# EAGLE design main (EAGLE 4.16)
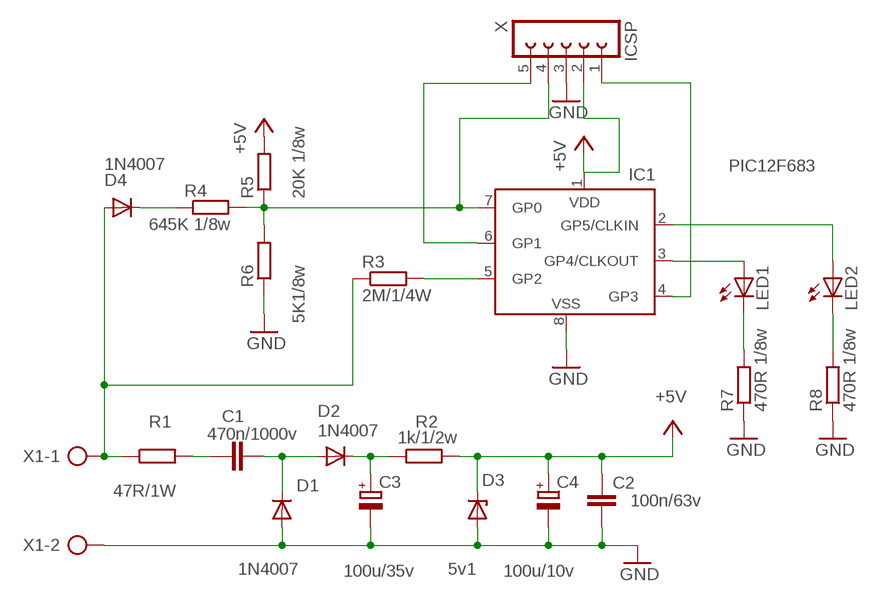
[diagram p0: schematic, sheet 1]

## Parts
C1  470n/1000v  C-EU225-113X268  [C225-113X268]
C2  100n/63v  C-EU050-025X075  [C050-025X075]
C3  100u/35v  CPOL-EUE2.5-6  [E2,5-6]
C4  100u/10v  CPOL-EUE3.5-8  [E3,5-8]
D1  1N4007  1N4004  [DO41-10]
D2  1N4007  1N4004  [DO41-10]
D3  5v1  ZENER-DIODEDO34-7  [DO34Z7]
D4  1N4007  1N4148  [DO35-10]
IC1  PIC12F683  PIC12F675SN  [SO-08]
LED1  LED3MM  [LED3MM]
LED2  LED3MM  [LED3MM]
R1  47R/1W  R-EU_0617/22  [0617/22]
R2  1k/1/2w  R-EU_0207/12  [0207/12]
R3  2M/1/4W  R-EU_0207/10  [0207/10]
R4  645K 1/8w  R-EU_0207/10  [0207/10]
R5  20K 1/8w  R-EU_0207/10  [0207/10]
R6  5K1/8w  R-EU_0207/10  [0207/10]
R7  470R 1/8w  R-EU_0207/10  [0207/10]
R8  470R 1/8w  R-EU_0207/10  [0207/10]
X  ICSP  FE05-1  [FE05-1]
X1  AK300/2  [AK300/2]

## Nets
+5V: C2.1 C4.+ D3.C IC1.1(VDD) R2.2 R5.2 X.2
GND: C2.2 C3.- C4.- D1.A D3.A IC1.8(VSS) R6.1 R7.1 R8.1 X1.2 X.3
N$1: C1.1 R1.2
N$2: C1.2 D1.C D2.A
N$3: C3.+ D2.C R2.1
N$4: D4.A R1.1 R3.1 X1.1
N$5: IC1.7(GP0) R4.2 R5.1 R6.2 X.4
N$6: D4.C R4.1
N$7: LED1.K(C) R7.2
N$8: LED2.K(C) R8.2
N$9: IC1.3(GP4/CLKOUT) LED1.A
N$10: IC1.2(GP5/CLKIN) LED2.A
N$11: IC1.5(GP2) R3.2
N$12: IC1.4(GP3) X.1
X: IC1.6(GP1) X.5

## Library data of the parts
C1 C2 = rcl:C-EU: CAPACITOR, European symbol
C3 C4 = rcl:CPOL-EU: POLARIZED CAPACITOR, European symbol
D1 D2 = diode:1N4004: DIODE
D3 = diode:ZENER-DIODE: Z-Diode
D4 = diode:1N4148: DIODE
IC1 = microchip:PIC12F6*: Data Sheet 8-Pin FLASH-Based 8-Bit CMOS Microcontrollers Source: http://www.microchip.com .. 41190c.pdf
LED1 LED2 = led:LED: LED
R1-R8 = rcl:R-EU_: RESISTOR, European symbol
X = con-lsta:FE05-1: FEMALE HEADER
X1 = con-ptr500:AK300/2: CONNECTOR

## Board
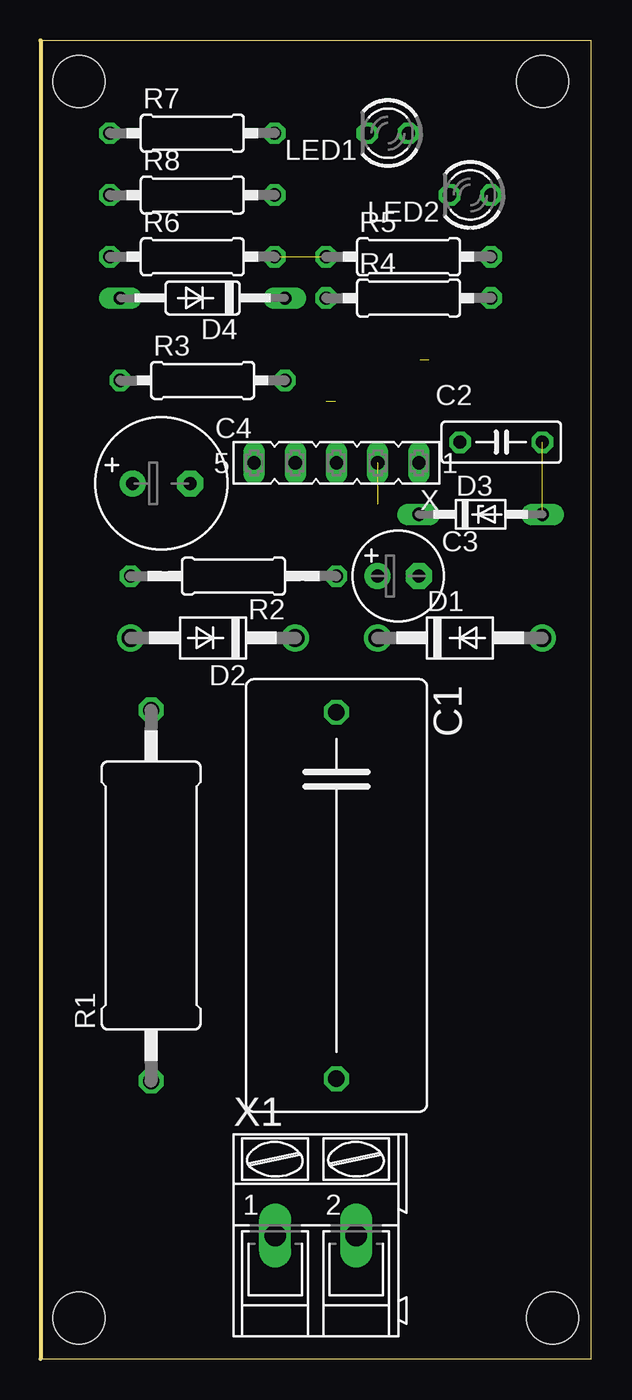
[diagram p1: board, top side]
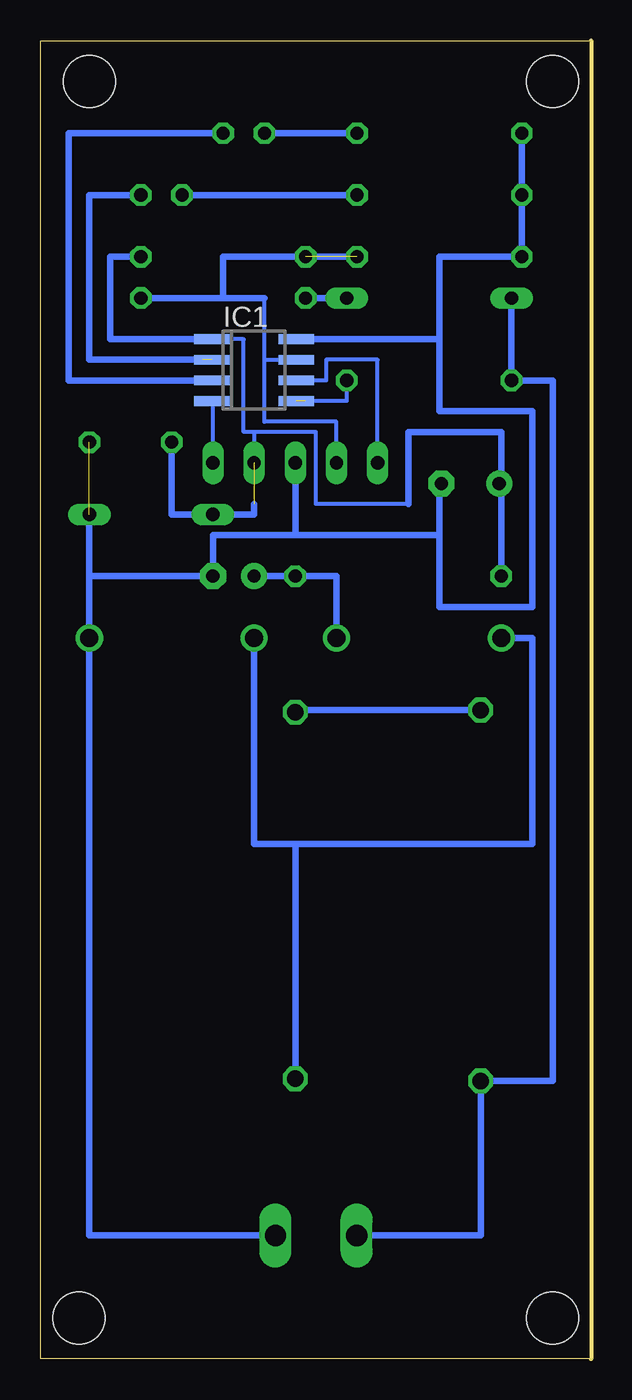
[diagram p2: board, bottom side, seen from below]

Size 33.96 x 81.27 mm. Coordinates in mm from the lower left corner, seen from the top.
Outline: 0,0 33.96,0 33.96,81.27 0,81.27 0,0
Copper layers (1*16): Top 0.035mm / dielectric 1.5mm / Bottom 0.035mm
Design rules "default": minimum track width 10mil, minimum drill 24mil, track to track 8mil, track to pad 8mil, pad to pad 8mil, via to via 8mil, smd to smd 8mil, copper to edge 40mil, drill to drill 8mil, minimum pad ring 10mil, minimum via ring 8mil, stop-mask expansion 4mil, vias tented up to drill 0mil, thermal gap 10mil
Holes 3.2 mm at 2.38,2.54 31.58,2.54 2.38,78.73 30.95,78.73 30.95,78.73 30.95,78.73

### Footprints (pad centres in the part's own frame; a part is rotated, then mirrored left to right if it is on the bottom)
C225-113X268 = drill 1.016 octagon: 1 -11.303,0; 2 11.303,0
C050-025X075 = drill 0.813 octagon: 1 -2.54,0; 2 2.54,0
E2,5-6 = drill 0.813 pad 1.6 round: + -1.27,0 | drill 0.813 pad 1.6 octagon: - 1.27,0
E3,5-8 = drill 0.813 pad 1.6 round: + -1.778,0 | drill 0.813 pad 1.6 octagon: - 1.778,0
DO41-10 = drill 1.118 round: A 5.08,0; C -5.08,0
DO34Z7 = drill 0.813 long: A 3.81,0; C -3.81,0
DO35-10 = drill 0.813 long: A 5.08,0; C -5.08,0
SO-08 = smd 0.6 x 2.2: 1 -1.905,-2.6; 2 -0.635,-2.6; 3 0.635,-2.6; 4 1.905,-2.6; 5 1.905,2.6; 6 0.635,2.6; 7 -0.635,2.6; 8 -1.905,2.6
LED3MM = drill 0.813 octagon: A -1.27,0; K 1.27,0
0617/22 = drill 1.016 octagon: 1 -11.43,0; 2 11.43,0
0207/12 = drill 0.813 octagon: 1 -6.35,0; 2 6.35,0
0207/10 = drill 0.813 octagon: 1 -5.08,0; 2 5.08,0
FE05-1 = drill 0.813 long: 1 -5.08,0; 2 -2.54,0; 3 0,0; 4 2.54,0; 5 5.08,0
AK300/2 = drill 1.321 long: 1 -2.515,0; 2 2.489,0

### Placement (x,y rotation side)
C1  18.25,28.57 270 top
C2  28.41,56.51 0 top
C3  22.06,48.26 0 top
C4  7.46,53.97 0 top
D1  25.87,44.45 0 top
D2  10.63,44.45 180 top
D3  27.14,52.07 0 top
D4  10,65.4 180 top
IC1  20.79,60.95 270 bottom
LED1  21.42,75.56 180 top
LED2  26.5,71.75 180 top
R1  6.82,28.57 90 top
R2  11.9,48.26 180 top
R3  10,60.32 0 top
R4  22.69,65.4 0 top
R5  22.69,67.94 0 top
R6  9.36,67.94 0 top
R7  9.36,75.56 0 top
R8  9.36,71.75 0 top
X  18.25,55.24 180 top
X1  16.98,7.62 0 top

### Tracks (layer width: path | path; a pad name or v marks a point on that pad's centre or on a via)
+5V  (1 unrouted)
  Bottom 0.254: IC1.1 21.42,62.86 21.42,57.15 20.79,57.15 | 11.27,52.7 16.98,52.7 16.98,57.15 20.79,57.15 | 20.79,57.15 X.2
  Bottom 0.406: R2.2 5.55,54.61 | 5.55,54.61 C4.+ | 5.55,54.61 5.55,57.15 11.27,57.15 11.27,52.7 | IC1.1 29.68,62.86 29.68,67.94 R5.2 | C2.1 25.87,52.07 D3.C 20.79,52.07 20.79,52.7
GND  (1 unrouted)
  Bottom 0.254: 9.36,53.34 C4.-
  Bottom 0.406: R6.1 R8.1 | R8.1 R7.1 | R6.1 R8.1 | X1.2 26.5,7.62 | 26.5,7.62 27.14,7.62 | R6.1 9.36,67.94 9.36,62.86 | 9.36,62.86 9.36,58.41 3.65,58.41 3.65,46.35 9.36,46.35 9.36,50.8 | 18.25,50.8 9.36,50.8 | 30.95,48.26 D3.A | 9.36,50.8 9.36,53.34 | 9.36,62.86 IC1.8 | 30.95,48.26 C3.- 23.33,50.8 18.25,50.8 | 30.95,48.26 D1.A 30.95,7.62 26.5,7.62 | 18.25,50.8 X.3
N$1
  Bottom 0.406: C1.1 18.25,40 R1.2
N$2
  Bottom 0.406: 18.25,19.05 C1.2 18.25,31.75 17.61,31.75 | 17.61,31.75 3.65,31.75 3.65,44.45 D2.A | D1.C 20.79,31.75 17.61,31.75
N$3
  Bottom 0.406: R2.1 C3.+ R2.1 | D2.C 15.71,48.26 R2.1
N$4
  Bottom 0.406: X1.1 6.82,7.62 R1.1 2.38,17.14 2.38,60.32 R3.1 D4.A
N$5  (1 unrouted)
  Bottom 0.254: X.4 15.71,57.78 20.15,57.78 20.15,61.59 | 20.15,61.59 IC1.7 | 20.15,61.59 20.15,65.4
  Bottom 0.406: R6.2 22.69,67.94 22.69,65.4 | 22.69,65.4 R4.2 | 20.15,65.4 22.69,65.4
N$6
  Bottom 0.406: D4.C R4.1
N$7
  Bottom 0.406: R7.2 LED1.K
N$8
  Bottom 0.406: R8.2 LED2.K
N$9
  Bottom 0.406: LED1.A 32.22,75.56 32.22,60.32 IC1.3
N$10  (1 unrouted)
  Bottom 0.406: LED2.A 30.95,71.75 30.95,61.59 23.96,61.59
N$11  (1 unrouted)
  Bottom 0.254: R3.2 15.08,59.05 17.61,59.05
N$12
  Bottom 0.254: IC1.4 23.33,59.05 X.1
X
  Bottom 0.254: X.5 13.17,61.59 16.34,61.59 16.34,60.32 IC1.6 18.25,60.32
